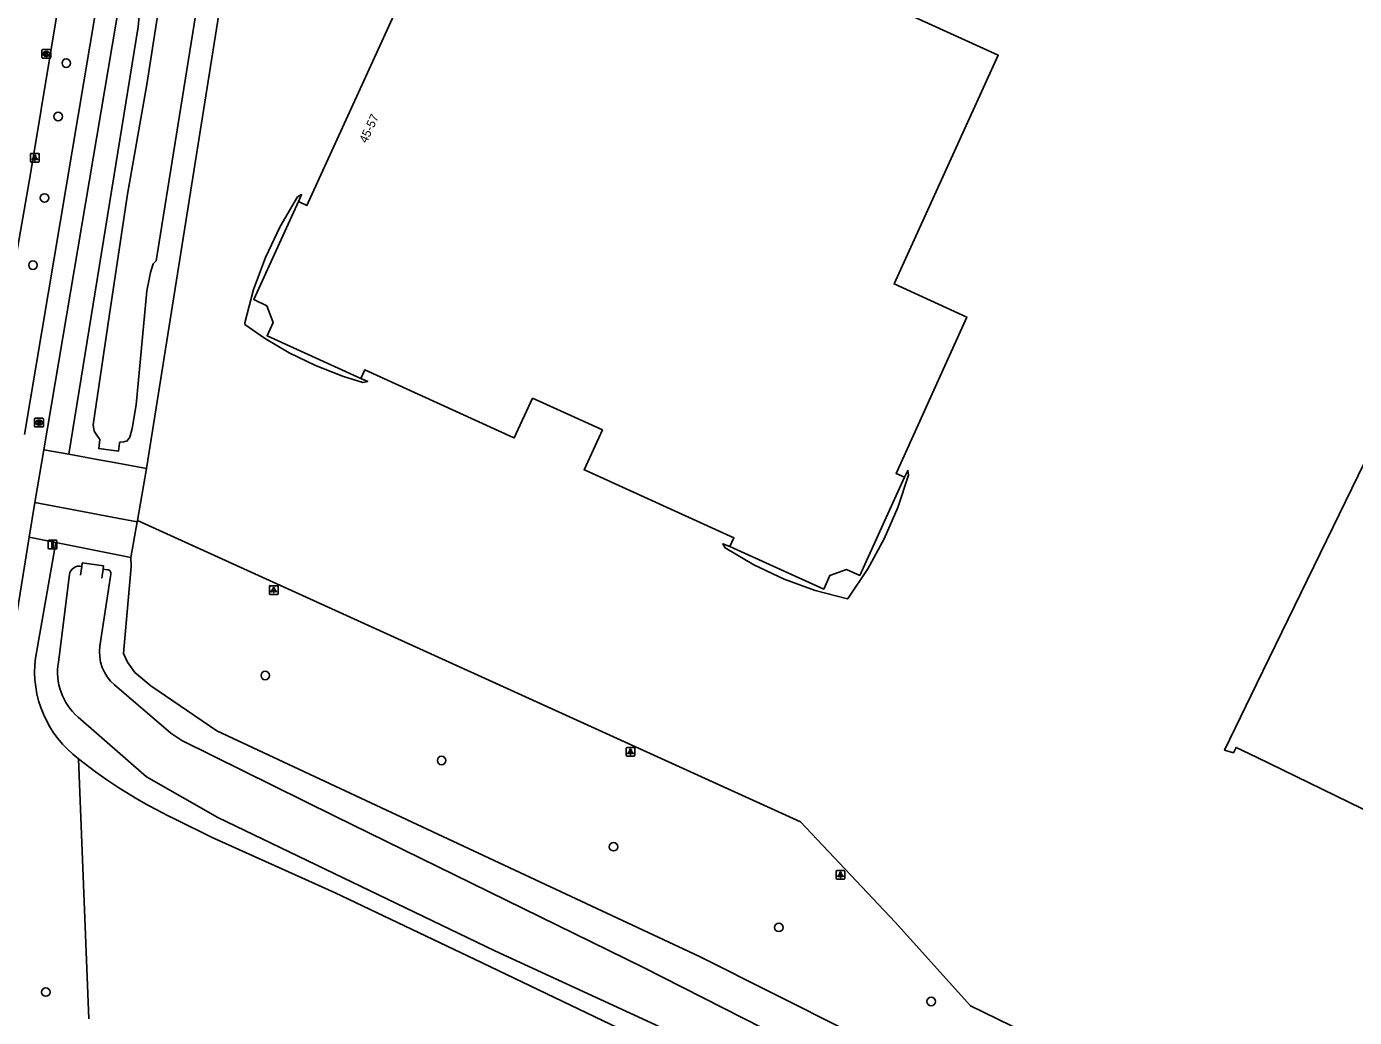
# Model space of a CAD drawing. Extents: x 156141 to 158132, y 385651 to 388399.
# Drawn here: x 156359.3 to 156511.2, y 386510.1 to 386623.5 of the extents above; entities that cross this region are included whole.
import ezdxf

# ---------------------------------------------------------------- set-up
doc = ezdxf.new("R2010")
doc.units = 0
for name, color, linetype in [('IMGEO_Afsluitpaal', 7, 'Continuous'), ('IMGEO_Berm_groen', 7, 'Continuous'), ('IMGEO_Boom', 7, 'Continuous'), ('IMGEO_Erf', 7, 'Continuous'), ('IMGEO_Fietspad_gesloten', 7, 'Continuous'), ('IMGEO_Groenvoorziening', 7, 'Continuous'), ('IMGEO_Hek', 7, 'Continuous'), ('IMGEO_Kolk', 7, 'Continuous'), ('IMGEO_Lichtpunt', 7, 'Continuous'), ('IMGEO_Loofbos', 7, 'Continuous'), ('IMGEO_Muur', 7, 'Continuous'), ('IMGEO_Pand', 7, 'Continuous'), ('IMGEO_Pand_nummerreeks', 7, 'Continuous'), ('IMGEO_Pand_overbouw', 7, 'Continuous'), ('IMGEO_Rijbaan_lokaal_gesloten', 7, 'Continuous'), ('IMGEO_Rijbaan_lokaal_open', 7, 'Continuous'), ('IMGEO_Rioolput', 7, 'Continuous'), ('IMGEO_Waterloop', 7, 'Continuous')]:
    doc.layers.add(name, color=color, linetype=linetype)

msp = doc.modelspace()

# ---------------------------------------------------------------- linework, layer by layer
at = {"layer": 'IMGEO_Afsluitpaal'}
for p, q in [((156361.8, 386563.79), (156361.8, 386564.59)), ((156361.8, 386564.59), (156361.8, 386563.79)), ((156361.9, 386564.69), (156362.69, 386564.69)), ((156362.69, 386564.69), (156361.9, 386564.69)), ((156362.69, 386563.69), (156361.9, 386563.69)), ((156361.9, 386563.69), (156362.69, 386563.69)), ((156362.79, 386564.59), (156362.79, 386563.79)), ((156362.79, 386563.79), (156362.79, 386564.59))]:
    msp.add_line(p, q, dxfattribs=at)
msp.add_lwpolyline([(156362.22, 386564.57), (156362.37, 386564.57), (156362.37, 386563.82), (156362.22, 386563.82), (156362.22, 386564.57)], dxfattribs=at)
for centre, start, end in [((156361.9, 386564.59), 90, 180), ((156361.9, 386564.59), 90, 180), ((156361.9, 386563.79), 180, 270), ((156361.9, 386563.79), 180, 270), ((156362.69, 386564.59), 0, 90), ((156362.69, 386564.59), 360, 90), ((156362.69, 386563.79), 270, 0), ((156362.69, 386563.79), 270, 0)]:
    msp.add_arc(centre, 0.1, start, end, dxfattribs=at)
at = {"layer": 'IMGEO_Berm_groen'}
msp.add_lwpolyline([(156364.16, 386574.52), (156372.08, 386623.41), (156372.36, 386626.45), (156372.42, 386630.11), (156373.85, 386638.32), (156374.96, 386644.65), (156376.09, 386651.59), (156376.9, 386656.44), (156377.46, 386658.5), (156377.9, 386660.08), (156378.46, 386661.73), (156378.64, 386661.96), (156378.94, 386662.31), (156379.49, 386662.8), (156380.34, 386663.14), (156381.5, 386663.2), (156383.05, 386663.04), (156383.83, 386662.86), (156384.78, 386662.18), (156385.6, 386661.37), (156386.29, 386660.36), (156386.75, 386659.15)], dxfattribs=at)
at = {"layer": 'IMGEO_Boom'}
for centre in [(156363.86, 386619.28), (156362.93, 386613.16), (156361.37, 386603.85), (156360.05, 386596.15), (156386.62, 386549.21), (156406.79, 386539.49), (156426.45, 386529.63), (156445.36, 386520.4), (156361.51, 386513), (156462.79, 386511.93)]:
    msp.add_circle(centre, 0.489, dxfattribs=at)
at = {"layer": 'IMGEO_Erf'}
msp.add_lwpolyline([(156373.05, 386572.88), (156386.75, 386659.15)], dxfattribs=at)
at = {"layer": 'IMGEO_Fietspad_gesloten'}
for points in [[(156359.07, 386576.8), (156374.01, 386665.7)], [(156361.28, 386575.05), (156376.48, 386664.82)], [(156359.62, 386565.04), (156360.26, 386568.99)], [(156354.92, 386509.47), (156354.07, 386509.75), (156356.29, 386537.7), (156357.35, 386551.05), (156359.62, 386565.04)]]:
    msp.add_lwpolyline(points, dxfattribs=at)
at = {"layer": 'IMGEO_Groenvoorziening'}
for points in [[(156371.97, 386566.79), (156371.25, 386562.72)], [(156371.99, 386566.95), (156447.85, 386532.48), (156458.65, 386520.98), (156467.27, 386511.43), (156654.66, 386420.01), (156654.6, 386419.89), (156819.39, 386339.6), (156839.51, 386329.8), (156877.29, 386311.4)], [(156362.67, 386564.43), (156359.62, 386565.04)], [(156362.67, 386564.43), (156360.32, 386551.21)], [(156371.25, 386562.72), (156362.67, 386564.43)], [(156470.28, 386500), (156436.29, 386517.05), (156381.06, 386542.89), (156373.54, 386548.05), (156371.71, 386549.54), (156370.85, 386550.76), (156370.42, 386551.75), (156371.29, 386561.67), (156371.25, 386562.72)]]:
    msp.add_lwpolyline(points, dxfattribs=at)
msp.add_arc((156372.74, 386549.71), 12.51, 173.0778, 233.221, dxfattribs=at)
at = {"layer": 'IMGEO_Hek'}
msp.add_lwpolyline([(156654.66, 386420.01), (156467.27, 386511.43), (156458.65, 386520.98)], dxfattribs=at)
at = {"layer": 'IMGEO_Kolk'}
for p, q in [((156361.08, 386619.9), (156361.08, 386620.75)), ((156361.15, 386620.83), (156362.01, 386620.83)), ((156362.01, 386619.83), (156361.15, 386619.83)), ((156361.59, 386620.05), (156361.56, 386620.05)), ((156361.57, 386620.61), (156361.59, 386620.61)), ((156362.08, 386620.75), (156362.08, 386619.9))]:
    msp.add_line(p, q, dxfattribs=at)
for points in [[(156361.08, 386619.9), (156361.08, 386620.75)], [(156361.15, 386620.83), (156362.01, 386620.83)], [(156362.01, 386619.83), (156361.15, 386619.83)], [(156361.4, 386620.53), (156361.52, 386620.53), (156361.52, 386620.37), (156361.65, 386620.53), (156361.82, 386620.53), (156361.67, 386620.38), (156361.82, 386620.13), (156361.67, 386620.13), (156361.59, 386620.29), (156361.52, 386620.22), (156361.52, 386620.13), (156361.4, 386620.13), (156361.4, 386620.53)], [(156362.08, 386620.75), (156362.08, 386619.9)]]:
    msp.add_lwpolyline(points, dxfattribs=at)
for centre, start, end in [((156361.16, 386620.75), 91.552, 178.448), ((156361.16, 386620.75), 91.552, 178.448), ((156361.16, 386619.9), 181.552, 268.448), ((156361.16, 386619.9), 181.552, 268.448), ((156362, 386620.75), 1.552, 88.448), ((156362, 386620.75), 1.552, 88.448), ((156362, 386619.9), 271.552, 358.448), ((156362, 386619.9), 271.552, 358.448)]:
    msp.add_arc(centre, 0.0765, start, end, dxfattribs=at)
for centre, major_axis, ratio, start_param, end_param in [((156361.57, 386620.33), (-0.387, 0.002), 0.722429, 4.712389, 7.853982), ((156361.59, 386620.33), (-0.39, 0.002), 0.717154, 1.570796, 4.712389)]:
    msp.add_ellipse(centre, major_axis=major_axis, ratio=ratio, start_param=start_param, end_param=end_param, dxfattribs=at)
at = {"layer": 'IMGEO_Lichtpunt'}
for p, q in [((156359.77, 386608.85), (156359.77, 386608.04)), ((156359.77, 386608.85), (156359.77, 386608.04)), ((156360.67, 386608.94), (156359.86, 386608.94)), ((156360.67, 386608.94), (156359.86, 386608.94)), ((156359.86, 386607.94), (156360.67, 386607.94)), ((156359.86, 386607.94), (156360.67, 386607.94)), ((156360.77, 386608.04), (156360.77, 386608.85)), ((156360.77, 386608.04), (156360.77, 386608.85)), ((156387.09, 386559.4), (156387.09, 386558.59)), ((156387.09, 386559.4), (156387.09, 386558.59)), ((156387.99, 386559.49), (156387.18, 386559.49)), ((156387.99, 386559.49), (156387.18, 386559.49)), ((156388.08, 386558.59), (156388.08, 386559.4)), ((156388.08, 386558.59), (156388.08, 386559.4)), ((156387.18, 386558.49), (156387.99, 386558.49)), ((156387.18, 386558.49), (156387.99, 386558.49)), ((156427.89, 386540.88), (156427.89, 386540.08)), ((156427.89, 386540.88), (156427.89, 386540.08)), ((156428.79, 386540.98), (156427.99, 386540.98)), ((156428.79, 386540.98), (156427.99, 386540.98)), ((156428.89, 386540.08), (156428.89, 386540.88)), ((156428.89, 386540.08), (156428.89, 386540.88)), ((156427.99, 386539.98), (156428.79, 386539.98)), ((156427.99, 386539.98), (156428.79, 386539.98)), ((156451.91, 386526.82), (156451.91, 386526.01)), ((156451.91, 386526.82), (156451.91, 386526.01)), ((156452.81, 386526.91), (156452.01, 386526.91)), ((156452.81, 386526.91), (156452.01, 386526.91)), ((156452.01, 386525.91), (156452.81, 386525.91)), ((156452.01, 386525.91), (156452.81, 386525.91)), ((156452.91, 386526.01), (156452.91, 386526.82)), ((156452.91, 386526.01), (156452.91, 386526.82))]:
    msp.add_line(p, q, dxfattribs=at)
for points in [[(156360.14, 386608.51), (156360.18, 386608.48), (156359.99, 386608.22), (156359.96, 386608.25), (156360.14, 386608.51)], [(156360.24, 386608.46), (156360.29, 386608.46), (156360.29, 386608.14), (156360.24, 386608.14), (156360.24, 386608.46)], [(156360.35, 386608.48), (156360.39, 386608.51), (156360.58, 386608.25), (156360.54, 386608.22), (156360.35, 386608.48)], [(156387.46, 386559.06), (156387.5, 386559.03), (156387.31, 386558.77), (156387.27, 386558.8), (156387.46, 386559.06)], [(156387.56, 386559.01), (156387.61, 386559.01), (156387.61, 386558.69), (156387.56, 386558.69), (156387.56, 386559.01)], [(156387.67, 386559.03), (156387.71, 386559.06), (156387.9, 386558.8), (156387.86, 386558.77), (156387.67, 386559.03)], [(156428.27, 386540.55), (156428.3, 386540.52), (156428.12, 386540.26), (156428.08, 386540.28), (156428.27, 386540.55)], [(156428.37, 386540.5), (156428.41, 386540.5), (156428.41, 386540.18), (156428.37, 386540.18), (156428.37, 386540.5)], [(156428.48, 386540.52), (156428.52, 386540.55), (156428.7, 386540.28), (156428.66, 386540.26), (156428.48, 386540.52)], [(156452.29, 386526.48), (156452.32, 386526.45), (156452.14, 386526.19), (156452.1, 386526.22), (156452.29, 386526.48)], [(156452.39, 386526.43), (156452.43, 386526.43), (156452.43, 386526.11), (156452.39, 386526.11), (156452.39, 386526.43)], [(156452.5, 386526.45), (156452.54, 386526.48), (156452.72, 386526.22), (156452.68, 386526.19), (156452.5, 386526.45)]]:
    msp.add_lwpolyline(points, dxfattribs=at)
for centre in [(156360.27, 386608.64), (156387.59, 386559.19), (156428.39, 386540.68), (156452.41, 386526.61)]:
    msp.add_circle(centre, 0.0994, dxfattribs=at)
for centre, start, end in [((156359.86, 386608.85), 90, 180), ((156359.86, 386608.85), 90, 180), ((156359.86, 386608.04), 180, 270), ((156359.86, 386608.04), 180, 270), ((156360.67, 386608.85), 0, 90), ((156360.67, 386608.85), 0, 90), ((156360.67, 386608.04), 270, 0), ((156360.67, 386608.04), 270, 360), ((156387.18, 386559.4), 90, 180), ((156387.18, 386559.4), 90, 180), ((156387.99, 386559.4), 0, 90), ((156387.99, 386559.4), 0, 90), ((156387.18, 386558.59), 180, 270), ((156387.18, 386558.59), 180, 270), ((156387.99, 386558.59), 270, 0), ((156387.99, 386558.59), 270, 360), ((156427.99, 386540.88), 90, 180), ((156427.99, 386540.88), 90, 180), ((156428.79, 386540.88), 0, 90), ((156428.79, 386540.88), 0, 90), ((156427.99, 386540.08), 180, 270), ((156427.99, 386540.08), 180, 270), ((156428.79, 386540.08), 270, 0), ((156428.79, 386540.08), 270, 360), ((156452.01, 386526.82), 90, 180), ((156452.01, 386526.82), 90, 180), ((156452.01, 386526.01), 180, 270), ((156452.01, 386526.01), 180, 270), ((156452.81, 386526.82), 0, 90), ((156452.81, 386526.82), 0, 90), ((156452.81, 386526.01), 270, 0), ((156452.81, 386526.01), 270, 360)]:
    msp.add_arc(centre, 0.0946, start, end, dxfattribs=at)
at = {"layer": 'IMGEO_Loofbos'}
for points in [[(156366.42, 386509.94), (156365.25, 386539.69)], [(156376.23, 386532.82), (156380.53, 386530.67), (156394.61, 386524.34), (156410.55, 386516.78), (156432.52, 386506.23), (156455.92, 386495.25), (156484.14, 386481.46), (156508.4, 386470.1), (156535.15, 386456.9), (156542.2, 386453.22), (156548.5, 386449.94), (156550.89, 386448.79), (156551.8, 386448.5), (156552.29, 386448.09)]]:
    msp.add_lwpolyline(points, dxfattribs=at)
msp.add_arc((156400.16, 386583.3), 55.86, 231.3244, 244.6442, dxfattribs=at)
at = {"layer": 'IMGEO_Muur'}
for points in [[(156367.7, 386576.22), (156367.57, 386575.18), (156369.82, 386574.87), (156369.93, 386575.8)], [(156365.48, 386560.68), (156365.63, 386561.7), (156365.68, 386562.1), (156368.11, 386561.78), (156368.06, 386561.37), (156367.92, 386560.34)]]:
    msp.add_lwpolyline(points, dxfattribs=at)
at = {"layer": 'IMGEO_Pand'}
for points in [[(156417.17, 386580.95), (156425.17, 386577.31), (156423.09, 386572.76), (156423.21, 386572.71), (156440.21, 386564.96), (156439.77, 386563.98), (156450.49, 386559.1), (156451.2, 386560.66), (156453.08, 386561.36), (156454.61, 386560.66), (156459.74, 386571.92), (156458.76, 386572.33), (156466.85, 386590.22), (156458.53, 386594.02), (156470.46, 386620.18), (156453.73, 386627.82)], [(156401.37, 386624.82), (156391.39, 386602.99), (156390.42, 386603.44), (156385.3, 386592.22), (156386.8, 386591.52), (156387.52, 386589.6), (156386.83, 386588.09), (156397.55, 386583.2), (156398.01, 386584.19), (156414.99, 386576.45), (156415.09, 386576.4), (156417.17, 386580.95)], [(156536.34, 386622.8), (156500, 386548.21), (156496.33, 386540.68), (156497.35, 386540.37), (156497.66, 386540.99), (156500, 386539.86), (156522.6, 386528.85)]]:
    msp.add_lwpolyline(points, dxfattribs=at)
at = {"layer": 'IMGEO_Pand_overbouw'}
for points in [[(156397.55, 386583.2), (156386.83, 386588.09), (156387.52, 386589.6), (156386.8, 386591.52), (156385.3, 386592.22), (156390.42, 386603.44), (156390.78, 386604.24), (156390.3, 386603.97), (156388.31, 386600.6), (156386.63, 386597.05), (156385.28, 386593.37), (156384.27, 386589.58), (156384.28, 386589.39), (156386.53, 386587.81), (156389.36, 386586.13), (156392.36, 386584.69), (156395.58, 386583.42), (156397.79, 386582.74), (156398.34, 386582.85)], [(156439.77, 386563.98), (156438.95, 386564.29), (156439.23, 386563.82), (156442.5, 386561.88), (156445.95, 386560.24), (156449.53, 386558.94), (156453.22, 386557.98), (156453.36, 386558.17), (156455.54, 386561.41), (156457.42, 386564.84), (156458.98, 386568.42), (156460.2, 386572.14), (156460.12, 386572.67), (156459.74, 386571.92), (156454.61, 386560.66), (156453.08, 386561.36), (156451.2, 386560.66), (156450.49, 386559.1)]]:
    msp.add_lwpolyline(points, close=True, dxfattribs=at)
at = {"layer": 'IMGEO_Rijbaan_lokaal_gesloten'}
msp.add_lwpolyline([(156369.3, 386663.66), (156369.14, 386662.68), (156366.22, 386645.23), (156363.4, 386628.51), (156359.75, 386606.62), (156357.34, 386592.61), (156355.26, 386580.28)], dxfattribs=at)
at = {"layer": 'IMGEO_Rijbaan_lokaal_open'}
for points in [[(156360.26, 386568.99), (156361.28, 386575.05)], [(156361.28, 386575.05), (156364.16, 386574.52)], [(156364.16, 386574.52), (156367.39, 386573.92), (156369.33, 386573.57), (156373.05, 386572.88)], [(156373.05, 386572.88), (156371.99, 386566.95)], [(156371.97, 386566.79), (156368.5, 386567.45), (156366.53, 386567.82), (156360.26, 386568.99)], [(156371.99, 386566.95), (156371.97, 386566.79)]]:
    msp.add_lwpolyline(points, dxfattribs=at)
at = {"layer": 'IMGEO_Rioolput'}
for p, q in [((156360.24, 386577.73), (156360.24, 386578.58)), ((156360.31, 386578.65), (156361.16, 386578.65)), ((156361.16, 386577.65), (156360.31, 386577.65)), ((156360.72, 386578.43), (156360.75, 386578.43)), ((156360.75, 386577.87), (156360.72, 386577.87)), ((156361.24, 386578.58), (156361.24, 386577.73))]:
    msp.add_line(p, q, dxfattribs=at)
for points in [[(156360.24, 386577.73), (156360.24, 386578.58)], [(156360.31, 386578.65), (156361.16, 386578.65)], [(156361.16, 386577.65), (156360.31, 386577.65)], [(156360.82, 386578.35), (156360.57, 386578.35), (156360.57, 386577.95)], [(156360.57, 386577.95), (156360.7, 386577.95), (156360.7, 386578.12), (156360.71, 386578.12)], [(156360.75, 386578.27), (156360.7, 386578.27), (156360.7, 386578.19)], [(156360.7, 386578.19), (156360.75, 386578.19)], [(156360.75, 386578.09), (156360.83, 386577.95), (156360.96, 386577.95), (156360.9, 386578.08)], [(156361.24, 386578.58), (156361.24, 386577.73)]]:
    msp.add_lwpolyline(points, dxfattribs=at)
for centre, radius, start, end in [((156360.31, 386578.58), 0.0765, 91.552, 178.448), ((156360.31, 386578.58), 0.0765, 91.552, 178.448), ((156360.31, 386577.73), 0.0765, 181.552, 268.448), ((156360.31, 386577.73), 0.0765, 181.552, 268.448), ((156360.71, 386578.06), 0.0533, 26.0293, 88.6989), ((156360.76, 386578.18), 0.0964, 77.0061, 93.1865), ((156360.73, 386578.38), 0.19, 274.7715, 282.9687), ((156360.77, 386578.23), 0.0378, 276.6634, 79.6772), ((156360.82, 386578.24), 0.109, 350.3612, 89.416), ((156360.82, 386578.24), 0.112, 277.5842, 350.9817), ((156360.81, 386578.03), 0.108, 29.5134, 73.7905), ((156361.16, 386578.58), 0.0765, 1.552, 88.448), ((156361.16, 386578.58), 0.0765, 1.552, 88.448), ((156361.16, 386577.73), 0.0765, 271.552, 358.448), ((156361.16, 386577.73), 0.0765, 271.552, 358.448)]:
    msp.add_arc(centre, radius, start, end, dxfattribs=at)
for centre, major_axis, ratio, start_param, end_param in [((156360.72, 386578.15), (-0.387, 0.002), 0.722429, 4.712389, 7.853982), ((156360.75, 386578.15), (-0.39, 0.002), 0.717154, 1.570796, 4.712389)]:
    msp.add_ellipse(centre, major_axis=major_axis, ratio=ratio, start_param=start_param, end_param=end_param, dxfattribs=at)
at = {"layer": 'IMGEO_Waterloop'}
for points in [[(156376.7, 386640.11), (156373.08, 386616.82), (156370.86, 386604.28), (156368.76, 386590.3), (156366.93, 386577.9), (156367.03, 386577.16), (156367.35, 386576.7), (156367.7, 386576.22)], [(156367.7, 386576.22), (156367.57, 386575.18), (156369.82, 386574.87), (156369.93, 386575.8), (156369.99, 386575.91), (156370.46, 386575.95), (156370.83, 386576.07), (156371.11, 386576.47), (156371.39, 386577.47), (156371.85, 386580.18), (156373.08, 386593.21), (156373.5, 386595.32), (156373.78, 386596.3), (156374.13, 386596.66), (156376.48, 386611.16), (156379.51, 386630.17)], [(156368.57, 386561.31), (156368.06, 386561.37), (156368.11, 386561.78), (156365.68, 386562.1), (156365.63, 386561.7)], [(156364.22, 386560.77), (156362.96, 386550.73)], [(156367.7, 386552.57), (156368.87, 386560.3), (156368.95, 386560.78)], [(156560.01, 386451.66), (156540.44, 386461.36), (156505.36, 386478.31), (156473.14, 386494.28), (156471.12, 386494.85), (156429.81, 386515.83), (156394.59, 386533.14), (156377.09, 386541.78), (156375.83, 386542.6), (156369.37, 386548.15)], [(156365.21, 386544.46), (156373.03, 386537.62), (156381.18, 386532.98), (156412.89, 386517.71), (156431.25, 386509.24), (156452.14, 386498.84), (156487.74, 386482.07), (156517.52, 386467.08), (156541.04, 386455.61), (156552.61, 386449.52)]]:
    msp.add_lwpolyline(points, dxfattribs=at)
for centre, radius, start, end in [((156365.34, 386560.6), 1.13, 75.1378, 171.6971), ((156368.56, 386560.9), 0.407, 342.9114, 89.5303), ((156372.57, 386551.88), 4.92, 171.876, 229.3098), ((156369.66, 386549.6), 6.8, 170.3592, 229.0548)]:
    msp.add_arc(centre, radius, start, end, dxfattribs=at)

# ---------------------------------------------------------------- texts
at = {"layer": 'IMGEO_Pand_nummerreeks'}
msp.add_text('45-57', height=1, rotation=65.4186, dxfattribs=at).set_placement((156398.22, 386610.04))

doc.saveas('drawing.dxf')
